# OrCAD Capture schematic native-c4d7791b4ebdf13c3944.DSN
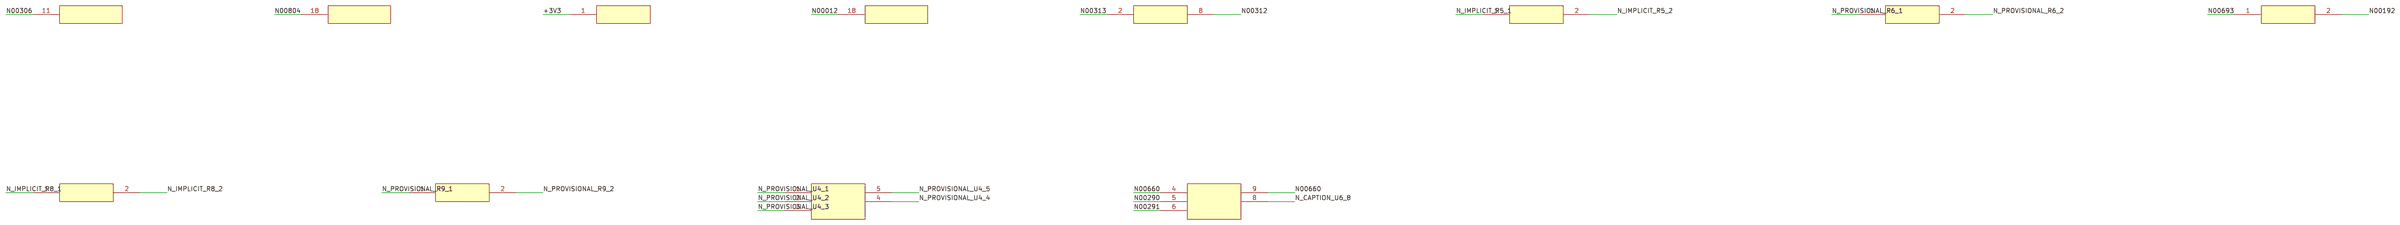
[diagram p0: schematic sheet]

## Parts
R4  10K
R5  220R
R6  220R
R7  52K
R8  220R
R9  220R
R11  10K
R16  220R
R17  10K
R18  10K
U4  SN74AUP1G125DRLR
U6  ATECC608A-MAHDA

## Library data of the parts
R4 = OBS_R4
R5 = OBS_R5
R6 = OBS_R6
R7 = OBS_R7
R8 = OBS_R8
R9 = OBS_R9
R11 = OBS_R11
R16 = OBS_R16
R17 = OBS_R17
R18 = OBS_R18
U4 = OBS_U4
U6 = OBS_U6

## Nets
+3V3: R17.1
N_CAPTION_U6_8: U6.8
N_IMPLICIT_R5_1: R5.1
N_IMPLICIT_R5_2: R5.2
N_IMPLICIT_R8_1: R8.1
N_IMPLICIT_R8_2: R8.2
N_PROVISIONAL_R6_1: R6.1
N_PROVISIONAL_R6_2: R6.2
N_PROVISIONAL_R9_1: R9.1
N_PROVISIONAL_R9_2: R9.2
N_PROVISIONAL_U4_1: U4.1
N_PROVISIONAL_U4_2: U4.2
N_PROVISIONAL_U4_3: U4.3
N_PROVISIONAL_U4_4: U4.4
N_PROVISIONAL_U4_5: U4.5
N00660: U6.4 U6.9

Not connected (* = marked no-connect by the designer): R4 2 8; R7 1 2; R11 11; R16 18; R18 18; U6 5 6
